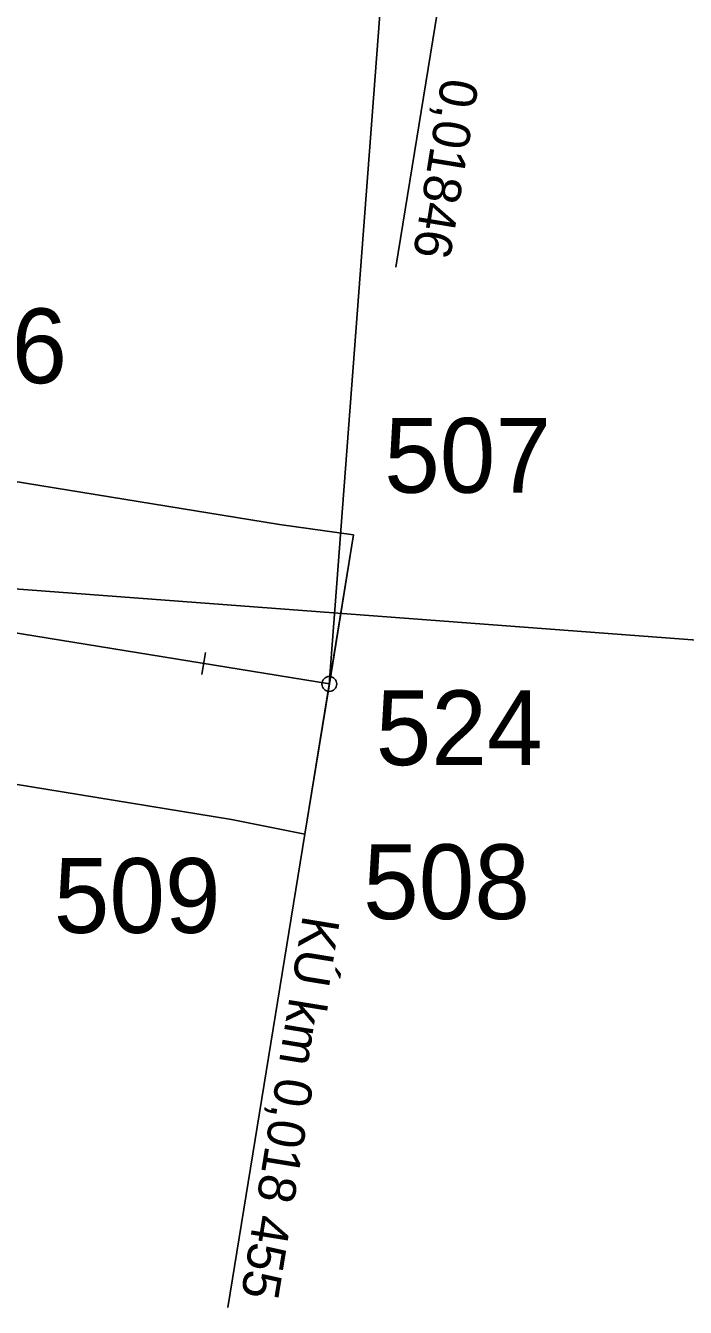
# Model space of a CAD drawing. Extents: x -743186.9 to -743133.1, y -1127113.3 to -1127042.8.
# Drawn here: x -743168.35 to -743159.52, y -1127107.75 to -1127090.61 of the extents above; entities that cross this region are included whole.
import ezdxf

# ---------------------------------------------------------------- set-up
doc = ezdxf.new("R2010")
doc.units = 0
for name, color, linetype in [('bublina_fialová_čára_tenká', 7, 'Continuous'), ('KOMUNIKACE_KRAJNICE', 7, 'Continuous'), ('křížek', 7, 'Continuous'), ('OSA_KOMUNIKACE', 7, 'Continuous'), ('OSA_POP', 7, 'Continuous'), ('SKLONOVNIKY', 7, 'Continuous'), ('SRAFA_UPRAVA', 7, 'Continuous'), ('Vrstva 60', 7, 'Continuous')]:
    doc.layers.add(name, color=color, linetype=linetype)

# ---------------------------------------------------------------- blocks, each defined once
blk = doc.blocks.new('AeccTickCircle')
blk.add_circle((0, 0), 0.5)
blk = doc.blocks.new('POINT_DISPLAY')
blk.add_line((0, 0), (0, 0))

msp = doc.modelspace()

# ---------------------------------------------------------------- linework, layer by layer
at = {"layer": 'bublina_fialová_čára_tenká'}
for p, q in [((-743160.679, -1127051.634), (-743164.286, -1127099.423)), ((-743148.502, -1127099.644), (-743174.29, -1127097.707))]:
    msp.add_line(p, q, dxfattribs=at)
at = {"layer": 'KOMUNIKACE_KRAJNICE'}
for p, q in [((-743164.95, -1127097.281), (-743171.211, -1127096.261)), ((-743164.95, -1127097.281), (-743163.96, -1127097.421)), ((-743164.612, -1127101.425), (-743163.96, -1127097.421)), ((-743165.593, -1127101.229), (-743173.53, -1127099.936)), ((-743165.593, -1127101.229), (-743164.612, -1127101.425))]:
    msp.add_line(p, q, dxfattribs=at)
at = {"layer": 'OSA_KOMUNIKACE'}
msp.add_line((-743164.284, -1127099.415), (-743182.5, -1127096.45), dxfattribs=at)
at = {"layer": 'OSA_POP'}
for p, q in [((-743165.99, -1127099.29), (-743165.941, -1127098.994)), ((-743164.612, -1127101.425), (-743165.642, -1127107.754))]:
    msp.add_line(p, q, dxfattribs=at)
at = {"layer": 'SKLONOVNIKY'}
msp.add_line((-743163.394, -1127093.841), (-743162.751, -1127089.893), dxfattribs=at)
at = {"layer": 'SRAFA_UPRAVA'}
for p, q in [((-743164.95, -1127097.281), (-743171.211, -1127096.261)), ((-743163.96, -1127097.421), (-743164.95, -1127097.281)), ((-743164.284, -1127099.415), (-743163.96, -1127097.421)), ((-743172.37, -1127098.099), (-743164.284, -1127099.415)), ((-743164.284, -1127099.415), (-743172.37, -1127098.099)), ((-743164.612, -1127101.425), (-743164.284, -1127099.415)), ((-743173.53, -1127099.936), (-743165.593, -1127101.229)), ((-743165.593, -1127101.229), (-743164.612, -1127101.425))]:
    msp.add_line(p, q, dxfattribs=at)
at = {"layer": 'Vrstva 60'}
for p, q in [((-743163.96, -1127097.421), (-743163.96, -1127097.421)), ((-743164.286, -1127099.423), (-743164.286, -1127099.423)), ((-743165.593, -1127101.229), (-743165.593, -1127101.229)), ((-743164.612, -1127101.425), (-743164.612, -1127101.425))]:
    msp.add_line(p, q, dxfattribs=at)

# ---------------------------------------------------------------- block references
at = {"layer": 'křížek', "xscale": 10, "yscale": 10, "rotation": 61.14491455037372}
for p in [(-743163.96, -1127097.421), (-743164.286, -1127099.423), (-743165.593, -1127101.229), (-743164.612, -1127101.425)]:
    msp.add_blockref('POINT_DISPLAY', p, dxfattribs=at)
at = {"layer": 'OSA_POP', "xscale": 0.2, "yscale": 0.19999999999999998, "rotation": -9.247996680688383}
msp.add_blockref('AeccTickCircle', (-743164.284, -1127099.415), dxfattribs=at)

# ---------------------------------------------------------------- texts
at = {"layer": 'OSA_POP'}
msp.add_text('KÚ km 0,018 455', height=0.5, rotation=260.752, dxfattribs=at).set_placement((-743164.636, -1127102.497))
at = {"layer": 'SKLONOVNIKY'}
msp.add_text('0,01846', height=0.5, rotation=260.752, dxfattribs=at).set_placement((-743162.778, -1127091.293))
at = {"layer": 'Vrstva 60'}
for s, p in [('506', (-743170.024, -1127095.392)), ('507', (-743163.55, -1127096.857)), ('524', (-743163.663, -1127100.501)), ('508', (-743163.832, -1127102.56)), ('509', (-743167.97, -1127102.745))]:
    msp.add_text(s, height=1, dxfattribs=at).set_placement(p)

doc.saveas('drawing.dxf')
